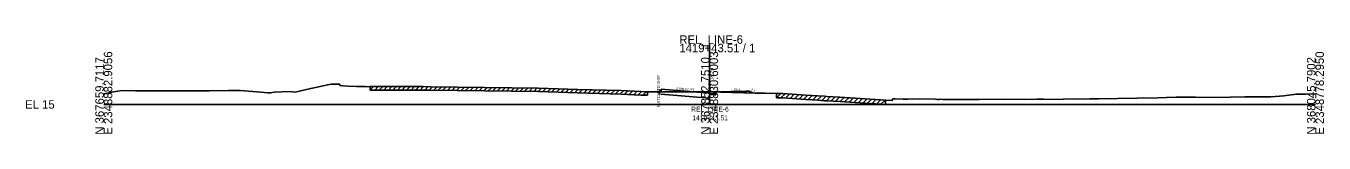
# Model space of a CAD drawing. Extents: x -26 to 403, y -10 to 6565.
# Drawn here: x -25.7 to 402.8, y 1490.3 to 1522.8 of the extents above; entities that cross this region are included whole.
import ezdxf

# ---------------------------------------------------------------- set-up
doc = ezdxf.new("R2010")
doc.units = 0
for name, color, linetype in [('RD_GPK_XS_Cell', 7, 'Continuous'), ('RD_XS_Base', 7, 'Continuous'), ('RD_XS_CurbBase', 7, 'Continuous'), ('RD_XS_CurbFront', 7, 'Continuous'), ('RD_XS_CurbTop', 7, 'Continuous'), ('RD_XS_EarthShd', 7, 'Continuous'), ('RD_XS_ExGround', 7, 'Continuous'), ('RD_XS_ExPaveRet', 7, 'Continuous'), ('RD_XS_MatchLine', 7, 'Continuous'), ('RD_XS_Pave', 7, 'Continuous'), ('RD_XS_SW', 7, 'Continuous'), ('RD_XS_SWbase', 7, 'Continuous'), ('RD_XS_TieSlope', 7, 'Continuous'), ('RD_XS_TX_Elev_EX', 7, 'Continuous'), ('RD_XS_TX_Elev_PR', 7, 'Continuous'), ('RD_XS_TX_MatchLine', 7, 'Continuous'), ('RD_XS_TX_Slope', 7, 'Continuous'), ('RD_XS_TX_Station', 7, 'Continuous'), ('RD_XS_TX_TOC', 7, 'Continuous')]:
    doc.layers.add(name, color=color, linetype=linetype)

msp = doc.modelspace()

# ---------------------------------------------------------------- linework, layer by layer
at = {"layer": 'RD_GPK_XS_Cell'}
for p, q in [((200, 1500), (200, 1519.99)), ((0, 1500), (200, 1500)), ((200, 1500), (400, 1500))]:
    msp.add_line(p, q, dxfattribs=at)
at = {"layer": 'RD_XS_Base'}
for p, q in [((184, 1504.58), (183.5, 1504.62)), ((183.5, 1504.62), (183.5, 1503.43)), ((184, 1505.03), (184, 1504.58)), ((183.87, 1503.4), (200, 1502.11))]:
    msp.add_line(p, q, dxfattribs=at)
at = {"layer": 'RD_XS_CurbBase'}
for p, q in [((201.5, 1503.15), (200, 1503.23)), ((200, 1502.11), (200, 1503.23)), ((202, 1503.15), (201.5, 1503.15)), ((202, 1504.15), (202, 1503.15))]:
    msp.add_line(p, q, dxfattribs=at)
at = {"layer": 'RD_XS_CurbFront'}
msp.add_line((200, 1503.23), (200, 1503.73), dxfattribs=at)
at = {"layer": 'RD_XS_CurbTop'}
for p, q in [((200, 1503.75), (200, 1503.73)), ((200, 1503.73), (201.42, 1503.65)), ((201.42, 1503.65), (201.5, 1504.15)), ((201.5, 1504.15), (202, 1504.15))]:
    msp.add_line(p, q, dxfattribs=at)
at = {"layer": 'RD_XS_EarthShd'}
for p, q in [((202, 1504.15), (207, 1504.25)), ((212, 1504.35), (213, 1504.37))]:
    msp.add_line(p, q, dxfattribs=at)
at = {"layer": 'RD_XS_ExGround'}
msp.add_lwpolyline([(0, 1503.49), (3.2, 1504.14), (6.12, 1504.64), (10.42, 1504.51), (11.4, 1504.51), (21.11, 1504.51), (23.74, 1504.51), (32.12, 1504.5), (34.87, 1504.5), (41.19, 1504.58), (44.65, 1504.63), (45.15, 1504.62), (50.49, 1504.13), (54.11, 1503.84), (55.09, 1503.81), (56.21, 1504.03), (61.43, 1504.22), (63.13, 1504.06), (68.31, 1505.3), (73.93, 1506.5), (75.09, 1506.63), (77.5, 1506.66), (77.86, 1506.66), (78.02, 1506.25), (78.88, 1506.17), (80.64, 1506.06), (83.42, 1505.9), (85.74, 1505.89), (86.25, 1505.89), (86.41, 1505.79), (87.94, 1505.87), (103.76, 1505.89), (105.47, 1505.88), (107.88, 1505.85), (143.47, 1505.41), (156.36, 1504.96), (170.76, 1504.57), (177.32, 1504.22), (179.02, 1504.14), (179.44, 1504.14), (182.65, 1504.11), (184.69, 1504.13), (186.89, 1504.2), (188.94, 1504.18), (189.97, 1504.15), (191.38, 1504.14), (191.96, 1504.18), (192.55, 1504.17), (196.41, 1504.19), (199.62, 1504.26), (200, 1504.24), (203.69, 1504.04), (215.04, 1503.75), (218.39, 1503.68), (222.06, 1503.58), (224.16, 1503.58), (231.77, 1503.07), (235.73, 1502.82), (237.91, 1502.67), (238.71, 1502.63), (242.99, 1502.4), (251.3, 1501.81), (258.07, 1501.4), (260.28, 1501.31), (260.52, 1501.81), (261.26, 1501.81), (263.85, 1501.78), (265.46, 1501.76), (269.38, 1501.82), (274.58, 1501.72), (275.07, 1501.66), (275.77, 1501.67), (276.24, 1501.68), (277.04, 1501.67), (278.23, 1501.65), (284.99, 1501.66), (286.02, 1501.65), (289.03, 1501.67), (297.36, 1501.68), (304.01, 1501.67), (308.05, 1501.68), (310.22, 1501.74), (313.41, 1501.66), (320.28, 1501.88), (323.68, 1501.74), (325.48, 1501.8), (327.01, 1501.81), (328.23, 1501.8), (341.14, 1502.03), (343.23, 1502.21), (345.08, 1502.01), (350.83, 1502.3), (354.06, 1502.37), (355.49, 1502.36), (360.39, 1502.34), (367.38, 1502.33), (371.89, 1502.4), (376.73, 1502.47), (381.09, 1502.48), (385.23, 1502.51), (389.61, 1502.87), (393.64, 1503.43), (396.84, 1503.43), (400, 1503.46)], dxfattribs=at)
at = {"layer": 'RD_XS_ExPaveRet'}
for p, q in [((87.94, 1504.73), (89.09, 1505.87)), ((87.94, 1504.73), (87.94, 1505.87)), ((87.94, 1504.73), (103.76, 1504.75)), ((89.44, 1504.73), (90.59, 1505.87)), ((90.94, 1504.73), (92.09, 1505.88)), ((92.44, 1504.73), (93.59, 1505.88)), ((93.94, 1504.74), (95.09, 1505.88)), ((95.44, 1504.74), (96.59, 1505.88)), ((96.94, 1504.74), (98.09, 1505.88)), ((98.44, 1504.74), (99.59, 1505.89)), ((99.94, 1504.74), (101.09, 1505.89)), ((101.44, 1504.75), (102.59, 1505.89)), ((102.94, 1504.75), (104.08, 1505.89)), ((103.76, 1504.75), (105.47, 1504.74)), ((104.44, 1504.75), (105.58, 1505.88)), ((105.47, 1504.74), (107.88, 1504.71)), ((105.94, 1504.73), (107.07, 1505.86)), ((107.44, 1504.72), (108.57, 1505.84)), ((107.88, 1504.71), (143.47, 1504.27)), ((108.94, 1504.7), (110.07, 1505.83)), ((110.44, 1504.68), (111.57, 1505.81)), ((111.94, 1504.66), (113.07, 1505.79)), ((113.44, 1504.64), (114.57, 1505.77)), ((114.94, 1504.62), (116.07, 1505.75)), ((116.44, 1504.6), (117.57, 1505.73)), ((117.94, 1504.59), (119.07, 1505.71)), ((119.44, 1504.57), (120.57, 1505.7)), ((120.94, 1504.55), (122.07, 1505.68)), ((122.44, 1504.53), (123.57, 1505.66)), ((123.94, 1504.51), (125.07, 1505.64)), ((125.44, 1504.49), (126.57, 1505.62)), ((126.94, 1504.47), (128.07, 1505.6)), ((128.44, 1504.46), (129.57, 1505.59)), ((129.94, 1504.44), (131.07, 1505.57)), ((131.44, 1504.42), (132.57, 1505.55)), ((132.94, 1504.4), (134.07, 1505.53)), ((134.44, 1504.38), (135.57, 1505.51)), ((135.94, 1504.36), (137.07, 1505.49)), ((137.44, 1504.34), (138.57, 1505.47)), ((138.94, 1504.33), (140.07, 1505.46)), ((140.44, 1504.31), (141.57, 1505.44)), ((141.94, 1504.29), (143.07, 1505.42)), ((143.44, 1504.27), (144.55, 1505.38)), ((143.47, 1504.27), (156.36, 1503.81)), ((144.94, 1504.22), (146.04, 1505.32)), ((146.44, 1504.16), (147.54, 1505.27)), ((147.94, 1504.11), (149.04, 1505.22)), ((149.44, 1504.06), (150.54, 1505.16)), ((150.94, 1504.01), (152.04, 1505.11)), ((152.44, 1503.95), (153.54, 1505.06)), ((153.94, 1503.9), (155.04, 1505)), ((155.44, 1503.85), (156.55, 1504.95)), ((156.94, 1503.8), (158.05, 1504.91)), ((158.44, 1503.76), (159.55, 1504.87)), ((159.94, 1503.72), (161.05, 1504.83)), ((161.44, 1503.68), (162.55, 1504.79)), ((162.94, 1503.64), (164.05, 1504.75)), ((164.44, 1503.6), (165.55, 1504.71)), ((165.94, 1503.56), (167.05, 1504.67)), ((167.44, 1503.52), (168.55, 1504.63)), ((168.94, 1503.48), (170.05, 1504.59)), ((170.44, 1503.44), (171.53, 1504.53)), ((171.94, 1503.37), (173.02, 1504.45)), ((173.44, 1503.29), (174.52, 1504.37)), ((174.94, 1503.2), (176.02, 1504.29)), ((176.44, 1503.12), (177.53, 1504.21)), ((156.36, 1503.81), (170.76, 1503.43)), ((170.76, 1503.43), (177.32, 1503.07)), ((177.32, 1503.07), (179.02, 1503)), ((177.94, 1503.05), (179.04, 1504.14)), ((179.02, 1503), (179.44, 1503)), ((179.44, 1504.14), (179.44, 1503)), ((222.06, 1502.14), (223.5, 1503.58)), ((222.06, 1502.14), (222.06, 1503.58)), ((222.06, 1502.14), (224.16, 1502.14)), ((223.56, 1502.14), (224.95, 1503.52)), ((224.16, 1502.14), (231.77, 1501.63)), ((225.06, 1502.08), (226.41, 1503.43)), ((226.56, 1501.98), (227.91, 1503.33)), ((228.06, 1501.88), (229.41, 1503.23)), ((229.56, 1501.78), (230.91, 1503.13)), ((231.06, 1501.68), (232.41, 1503.03)), ((231.77, 1501.63), (235.73, 1501.38)), ((232.56, 1501.58), (233.91, 1502.93)), ((234.06, 1501.49), (235.41, 1502.84)), ((235.56, 1501.39), (236.91, 1502.74)), ((235.73, 1501.38), (237.91, 1501.23)), ((237.06, 1501.29), (238.42, 1502.64)), ((237.91, 1501.23), (238.71, 1501.19)), ((238.56, 1501.2), (239.93, 1502.56)), ((238.71, 1501.19), (242.99, 1500.96)), ((240.06, 1501.12), (241.43, 1502.48)), ((241.56, 1501.04), (242.93, 1502.4)), ((242.99, 1500.96), (251.3, 1500.37)), ((243.06, 1500.95), (244.41, 1502.3)), ((244.56, 1500.85), (245.91, 1502.19)), ((246.06, 1500.74), (247.41, 1502.08)), ((247.56, 1500.64), (248.91, 1501.98)), ((249.06, 1500.53), (250.41, 1501.87)), ((250.56, 1500.42), (251.91, 1501.77)), ((251.3, 1500.37), (258.07, 1499.96)), ((252.06, 1500.32), (253.42, 1501.68)), ((253.56, 1500.23), (254.92, 1501.59)), ((255.06, 1500.14), (256.42, 1501.5)), ((256.56, 1500.05), (257.92, 1501.41)), ((258.07, 1501.4), (258.07, 1499.96))]:
    msp.add_line(p, q, dxfattribs=at)
at = {"layer": 'RD_XS_MatchLine'}
msp.add_line((184, 1505.03), (184, 1504.12), dxfattribs=at)
at = {"layer": 'RD_XS_Pave'}
msp.add_line((184, 1505.03), (200, 1503.75), dxfattribs=at)
at = {"layer": 'RD_XS_SW'}
msp.add_line((207, 1504.25), (212, 1504.35), dxfattribs=at)
at = {"layer": 'RD_XS_SWbase'}
for p, q in [((207, 1503.91), (207, 1504.25)), ((212, 1504.35), (212, 1504.01)), ((212, 1504.01), (207, 1503.91))]:
    msp.add_line(p, q, dxfattribs=at)
at = {"layer": 'RD_XS_TieSlope'}
msp.add_line((213, 1504.37), (214.19, 1503.77), dxfattribs=at)

# ---------------------------------------------------------------- texts
at = {"layer": 'RD_GPK_XS_Cell'}
for s, p in [('REL_LINE-6', (190, 1519.99)), ('1419+43.51 / 1', (190, 1517.19)), ('EL 15', (-26, 1498.6))]:
    msp.add_text(s, height=2.8, dxfattribs=at).set_placement(p)
for s, p in [('E 2348882.9056', (2.8, 1490)), ('E 2348830.6003', (202.8, 1490)), ('E 2348778.2950', (402.8, 1490)), ('N 367659.7117', (0, 1490)), ('N 367852.7510', (200, 1490)), ('N 368045.7902', (400, 1490))]:
    msp.add_text(s, height=2.8, rotation=90, dxfattribs=at).set_placement(p)
at = {"layer": 'RD_XS_TX_Elev_EX'}
msp.add_text('19.24', height=1, rotation=90, dxfattribs=at).set_placement((200.5, 1504.24))
at = {"layer": 'RD_XS_TX_Elev_PR'}
msp.add_text(' 18.75', height=1.2, rotation=90, dxfattribs=at).set_placement((201.2, 1507.45))
at = {"layer": 'RD_XS_TX_MatchLine'}
msp.add_text('MATCH TO S-97', height=1, rotation=90, dxfattribs=at).set_placement((183.63, 1499.15))
at = {"layer": 'RD_XS_TX_Slope'}
for s, rotation, p in [('0.080 FT./FT.', 355.4261, (189, 1504.88)), ('50:1', 1.1458, (208.13, 1504.51)), ('2:1', 333.4349, (213.57, 1504.62))]:
    msp.add_text(s, height=0.75, rotation=rotation, dxfattribs=at).set_placement(p)
at = {"layer": 'RD_XS_TX_Station'}
for s, p in [('REL_LINE-6', (193.92, 1497.65)), ('1419+43.51', (194.3, 1494.75))]:
    msp.add_text(s, height=1.6, dxfattribs=at).set_placement(p)
at = {"layer": 'RD_XS_TX_TOC'}
msp.add_text('TOCRT', height=0.05, dxfattribs=at).set_placement((201.22, 1504.1))

doc.saveas('drawing.dxf')
